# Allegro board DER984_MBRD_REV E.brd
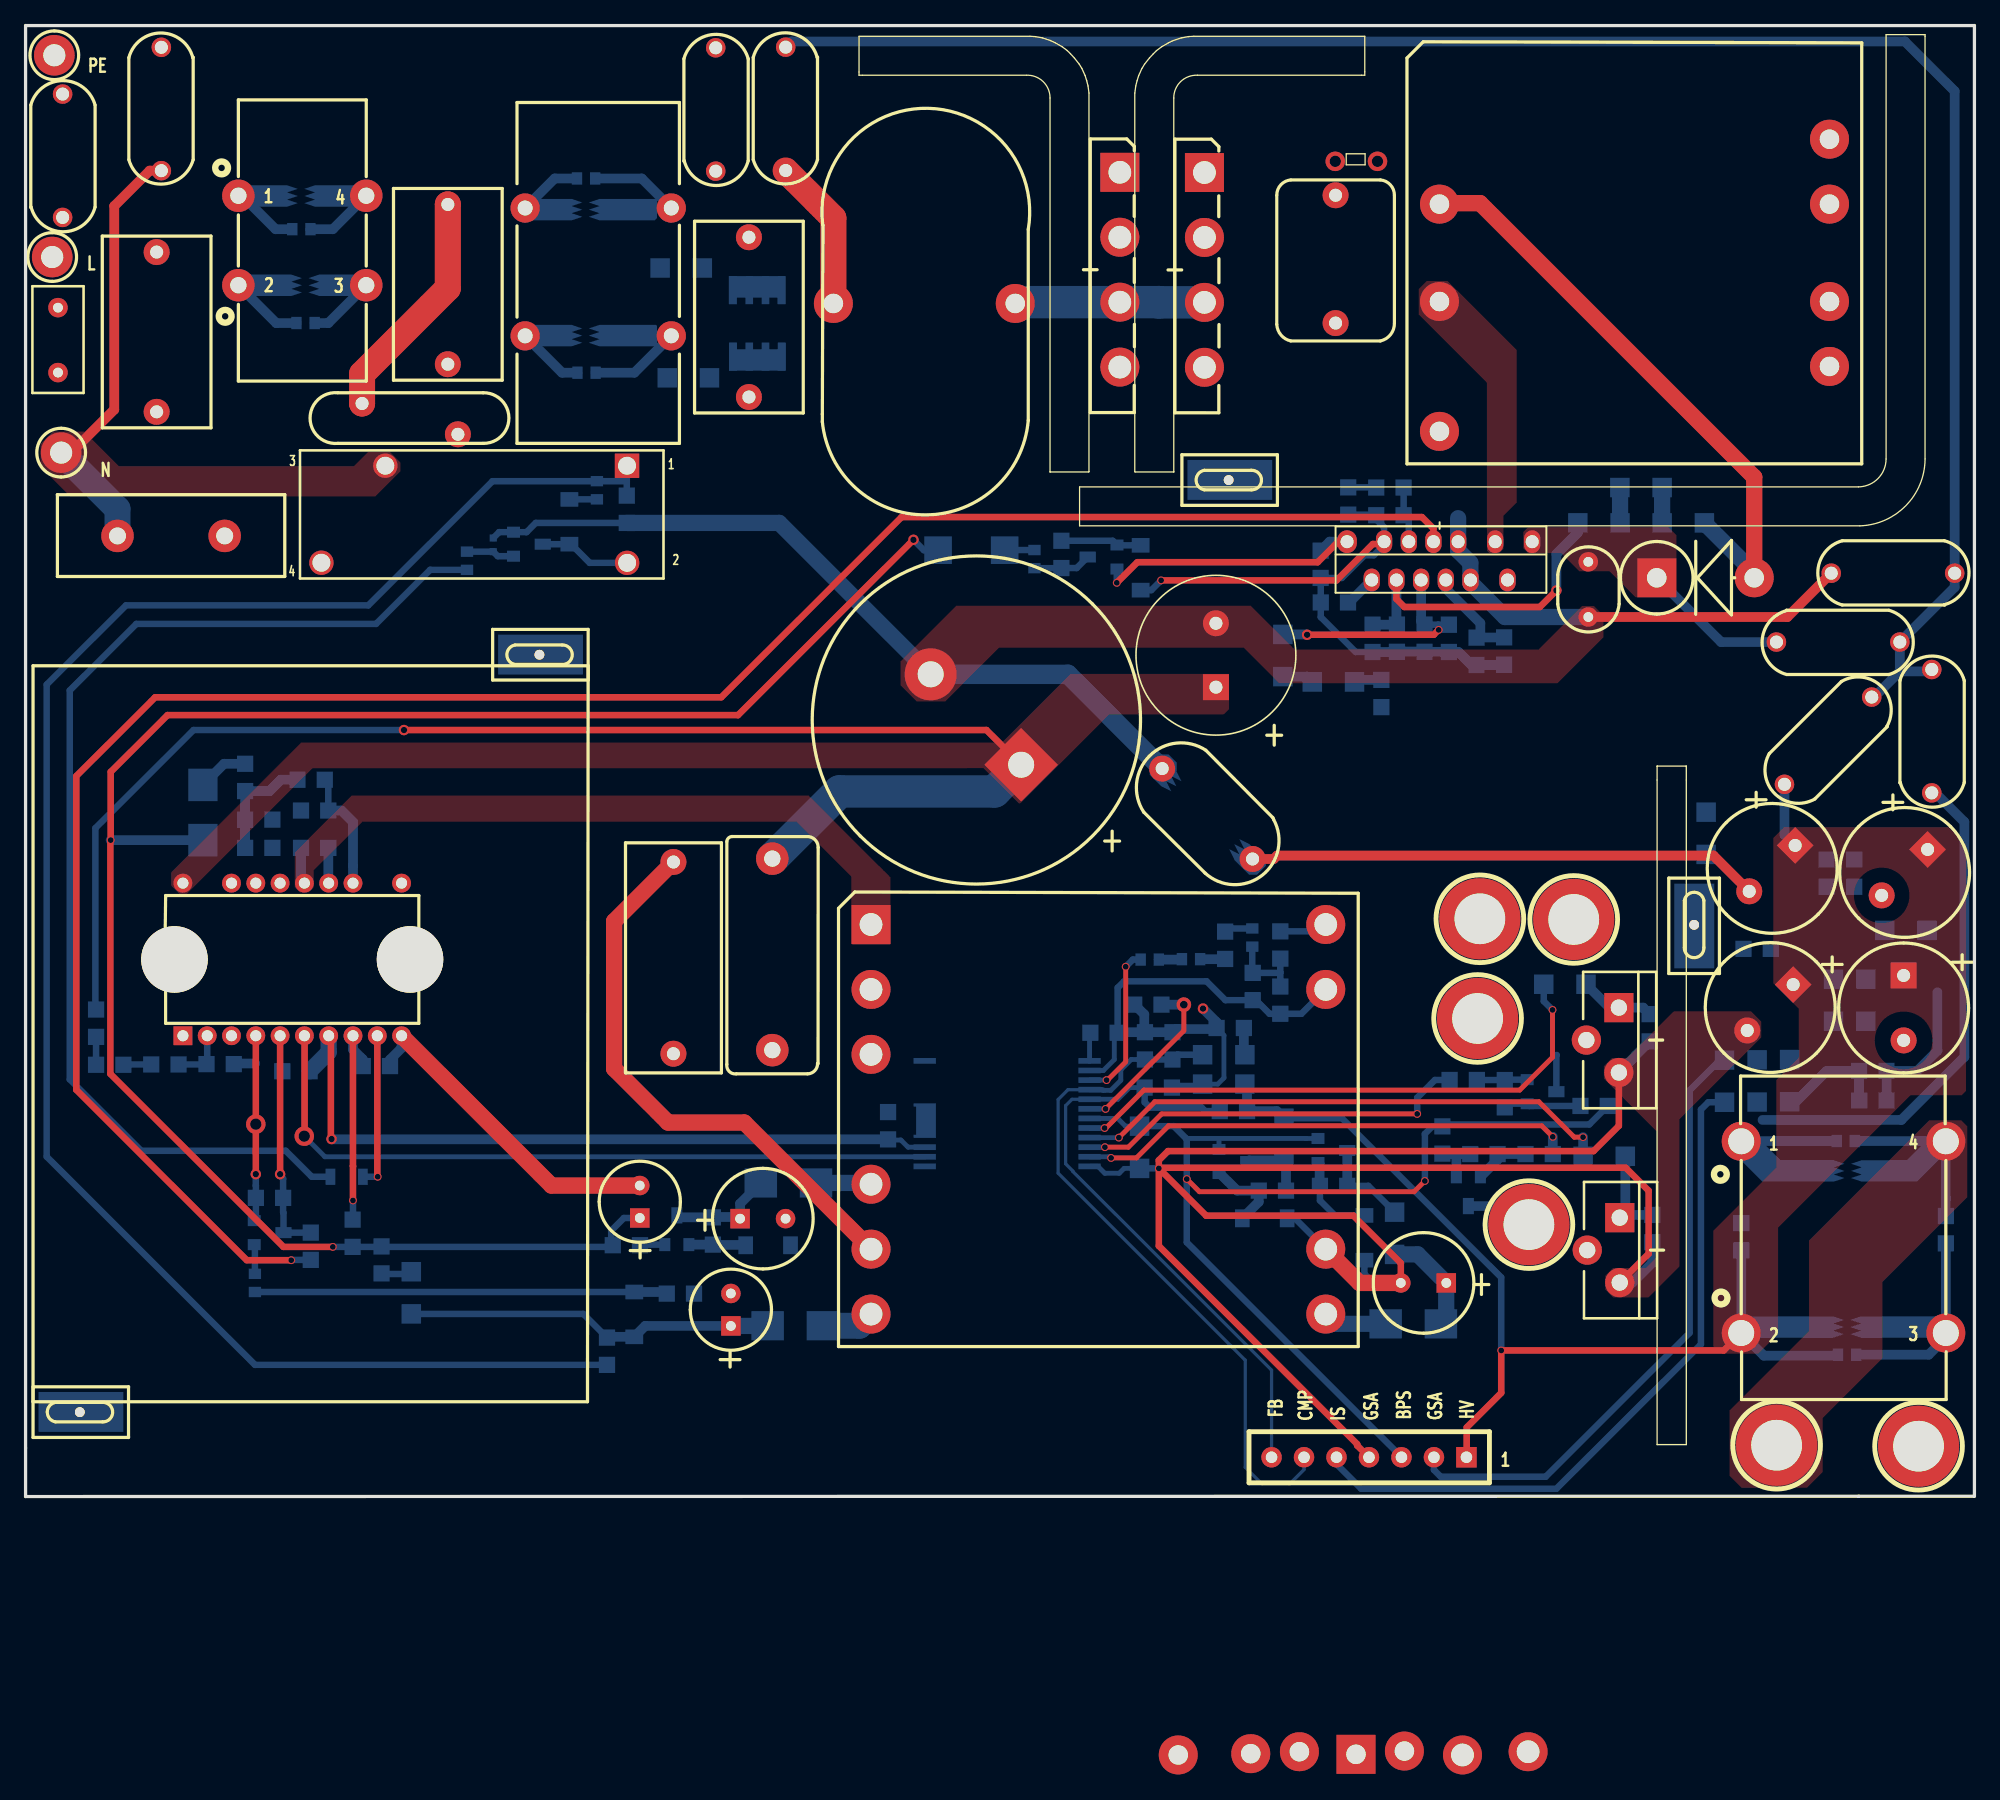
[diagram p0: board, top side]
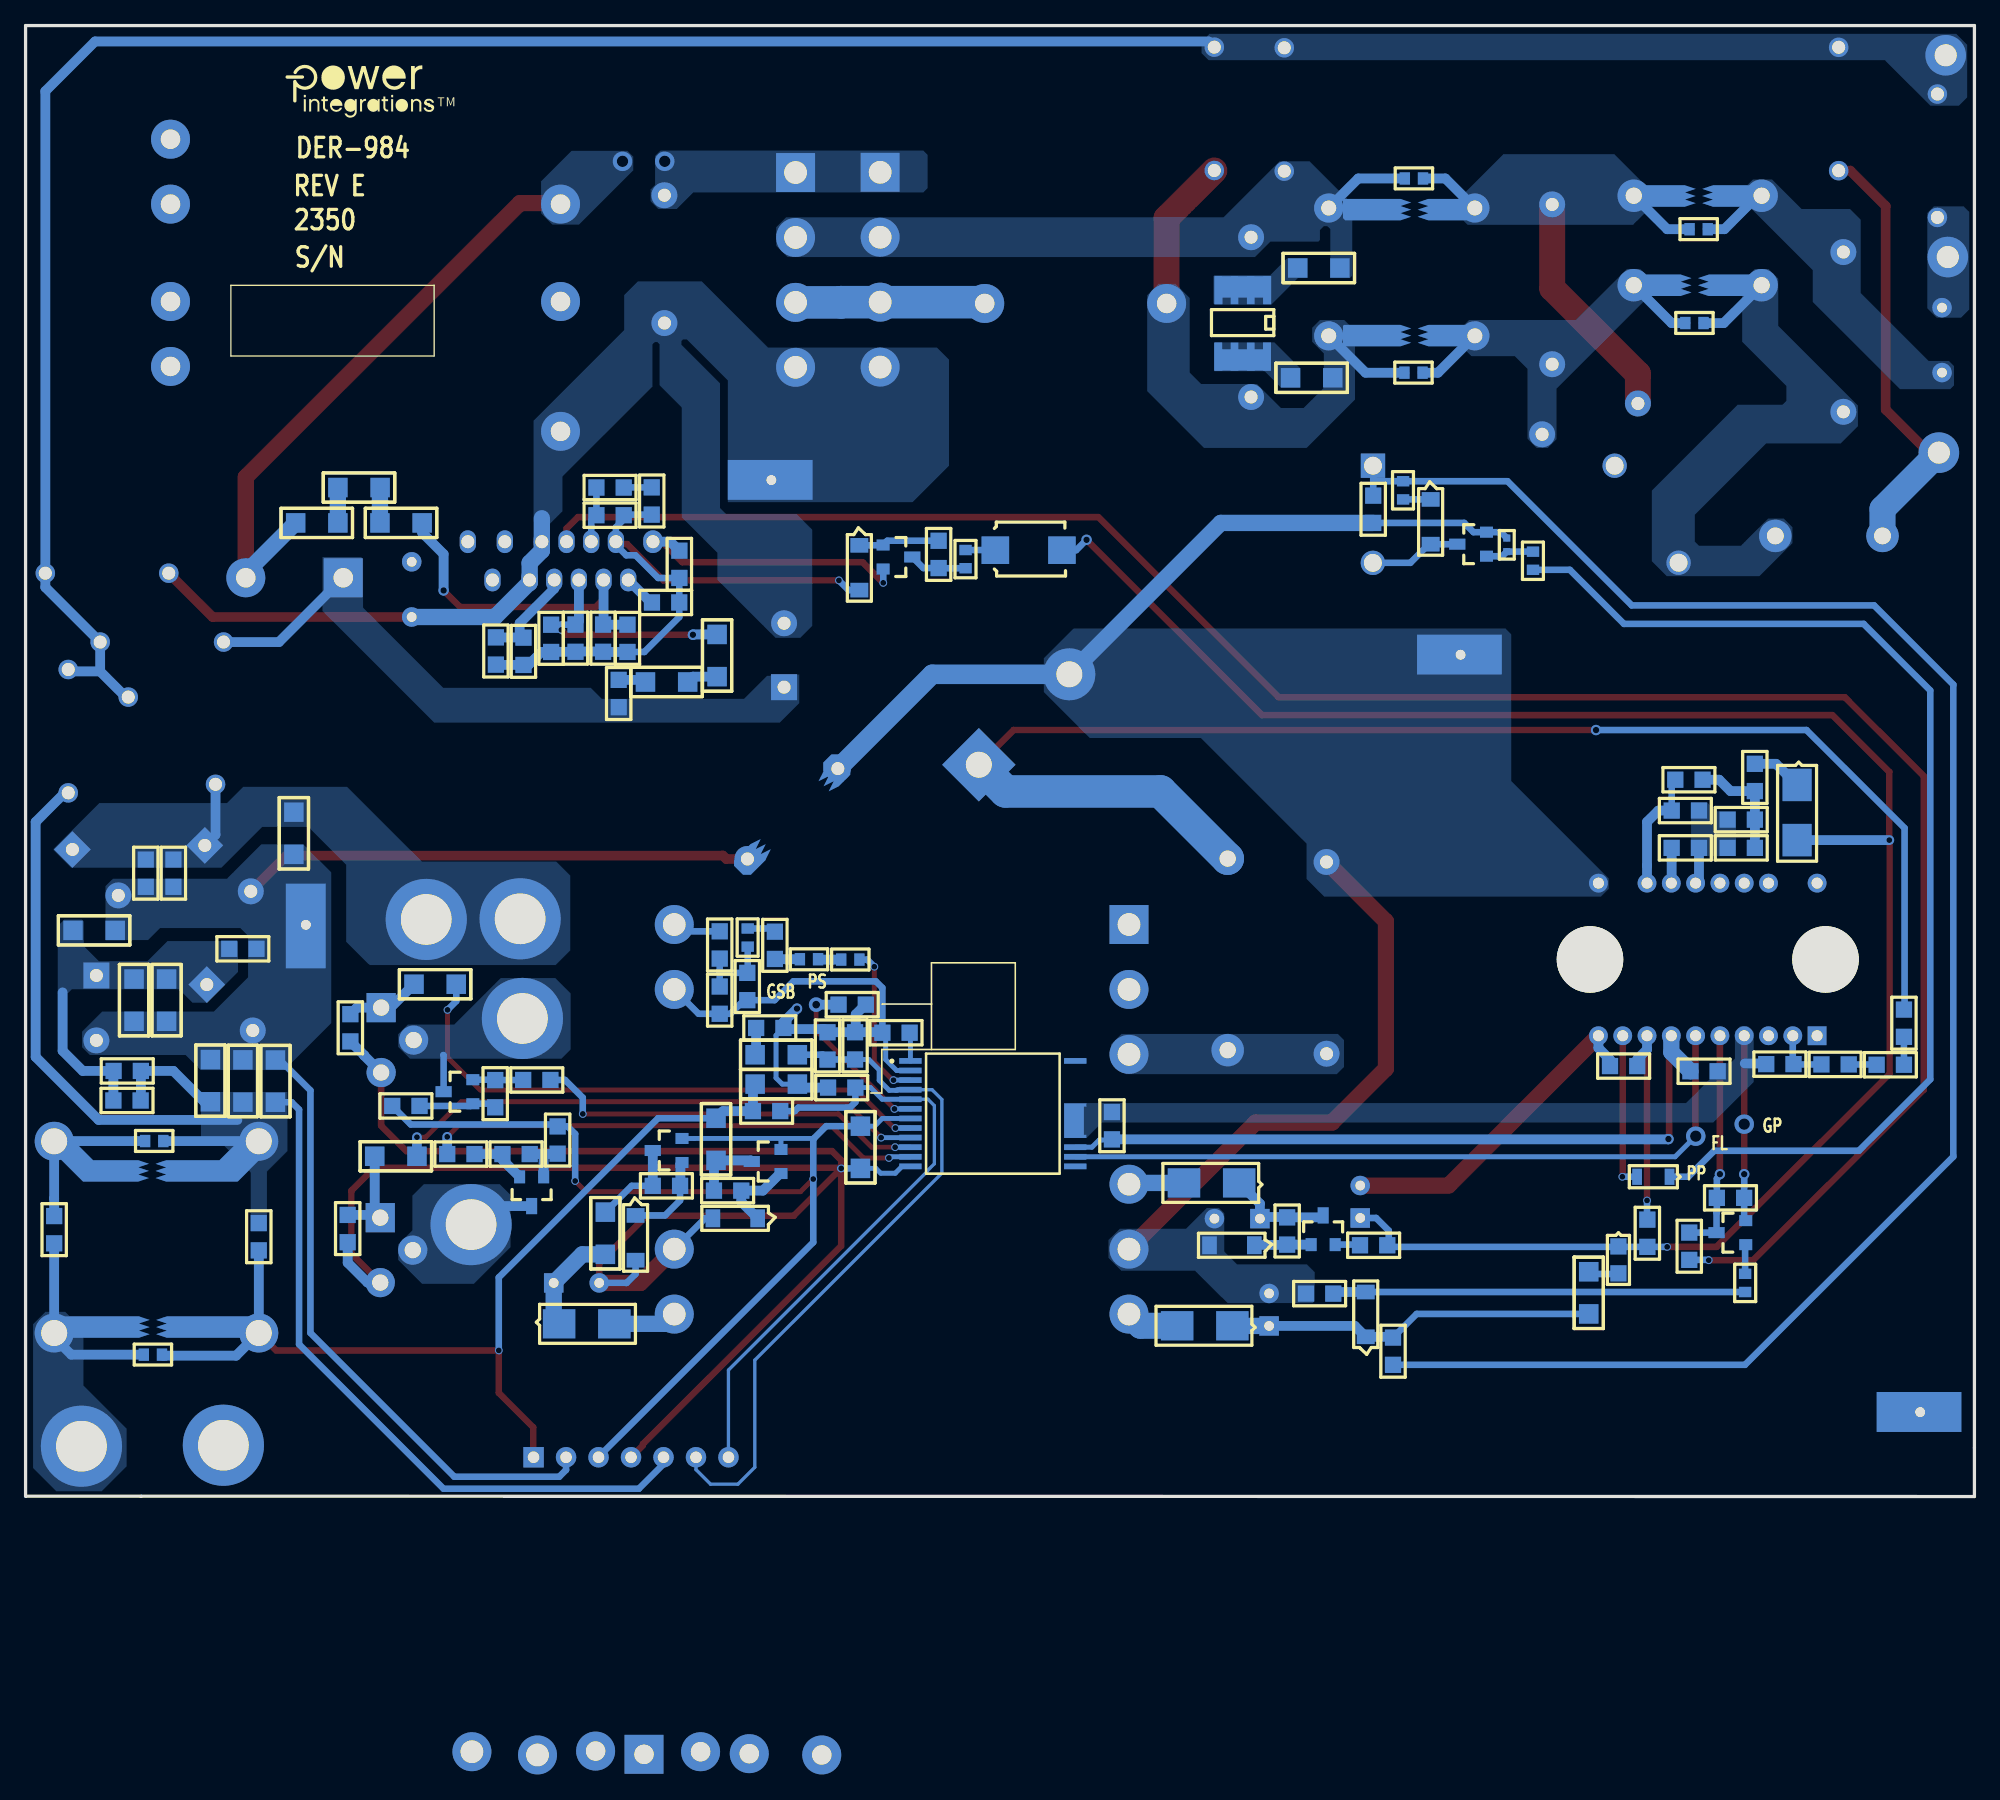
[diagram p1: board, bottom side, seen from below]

Outline 152.4 x 115.09 mm; copper layers: TOP, BOTTOM. Coordinates in mm from the lower left corner of the outline.
Outline path: 0,115.09 0,0 143.36,0.03 152.4,0.03 152.4,115.09 0,115.09

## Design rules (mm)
constraint set DEFAULT: min track width 0.254
net group 5VL: nets 5VL N12570782
net group N12371579: nets N12371579 N12371917
net group N12722777: nets N12722777 N12722869
net group 5VS: nets 5VS BOOST_OP_POS BP_RELAY CC_COMP IBSENSE N4415619 N11972126 N12371547 N12371615 N12371639 N12371737 N12371921 N12449925 N12461790 N12465647 N12472558 N12474629 OVP RTN VRECT
net group N4411203: nets N4411203

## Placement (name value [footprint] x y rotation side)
BR1  GBU8K-BP  [PIDAXBRIDGEGBU8]  92.19 103.59 270 top
BR2  GBU8K-BP  [PIDAXBRIDGEGBU8]  85.57 103.61 270 top
C1  1 uF  [PISMC0805]  21.54 53.67 0 bottom
C2  220 nF  [PISMC0805]  23.68 50.75 180 bottom
C3  100 uF  [PIPOLCAPCLYD320LS140030]  55.87 21.74 0 top
C4  10 uF  [PISMC0805]  17.17 50.75 0 bottom
C5  10 uF  [PISMC0805]  17.17 52.96 0 bottom
C7  1 uF  [PISMC0805]  26.37 33.68 0 bottom
C8  0.027 uF  [PINPXCAPRAD18X7P5MM040]  50.66 34.65 90 top
C10  150 uF  [PIPOLCAPCLYD320LS140030]  111.1 16.71 180 top
C11  220 uF  [PIPOLCAPCYLD400LS200040]  138.23 40.06 225 top
C12  100 uF  [PIPOLCAPCYLD250LS100030]  48.03 21.79 90 top
C13  100 uF  [PIPOLCAPCYLD250LS100030]  55.16 13.35 90 top
C14  1 uF  [PISMC0805]  22.21 33.27 180 bottom
C15  150 pF  [PINPCAPRAD394X275394030]  88.88 56.95 315 top
C16  1 uF  [PISMC0805]  136.48 42.85 180 bottom
C17  220 uF  [PIPOLCAPCYLD400LS200040]  138.38 50.94 225 top
C18  220 uF  [PIPOLCAPCYLD400LS200040]  148.74 50.62 225 top
C19  1 uF  [PISMC0805]  140.84 49.84 270 bottom
C20  1 uF  [PISMC0805]  143 49.84 270 bottom
C21  220 uF  [PIPOLCAPCYLD400LS200040]  146.86 40.77 270 top
C23  1.5 nF  [PISMC1206]  95.35 32.27 180 bottom
C24  10 uF  [PISMC1206]  87.11 28.98 270 bottom
C25  100 pF  [PISMC0805]  87.54 34.19 90 bottom
C26  2.2 nF  [PISMC0805]  95.27 36.66 180 bottom
C28  470 pF  [PISMC0603]  95.93 44.44 270 bottom
C30  100 nF  [PISMC0805]  67.44 27.95 90 bottom
C31  10 uF  [PISMC0805]  83.27 36.29 0 bottom
C32  680 pF  [PINPYCAPRAD470X210LS380040]  2.9 100.08 90 top
C33  680 pF  [PINPYCAPRAD470X210LS380040]  53.97 103.7 90 top
C34  1 uF  [PINPCAPRAD_12P6X9P2_LS10_D40]  102.44 101.81 270 top
C35  330 nF  [PINP_XCAPRAD15X8P5X14HD040]  33.02 101.09 270 top
C36  330 nF  [PINP_XCAPRAD15X8P5X14HD040]  56.57 98.53 270 top
C37  680 pF  [PINPYCAPRAD470X210LS380040]  59.44 113.4 270 top
C38  680 pF  [PINPYCAPRAD470X210LS380040]  10.62 113.39 270 top
C39  10 uF  [PISMC0805]  47.02 78.31 270 bottom
C40  220 uF  [PI_POLCAP_D1000LS394D080]  77.84 57.24 135 top
C41  10 nF  [PI_NP_CAP250X200LS170D030]  122.2 73.13 270 top
C42  100 nF  [PISMC0805]  107.76 76.78 180 bottom
C43  1 nF  [PISMC0805]  113.47 67.2 270 bottom
C44  1 uF  [PISMC0805]  103.42 69.95 180 bottom
C45  470 pF  [PISMC0805]  107.24 68.22 270 bottom
C46  1 uF  [PISMC0805]  103.43 78.96 270 bottom
C47  1 uF  [PISMC0805]  101.27 74 270 bottom
C48  470 pF  [PISMC0805]  109.4 68.22 270 bottom
C49  56 uF  [PIPOLCAPCLYD500LS200040]  93.09 63.32 90 top
C54  680 pf  [PISMC0805]  98.12 44.22 270 bottom
C58  6.8 nF  [PI_NP_CAPRAD709X276LS590D050]  58.39 49.91 270 top
C60  330 nF  [PINP_XCAPRAD15X8P5X14HD040]  10.25 97.37 270 top
C61  680 pF  [PINPYCAPRAD470X210LS380040]  136.92 66.85 0 top
C62  680 pF  [PINPYCAPRAD470X210LS380040]  150.86 72.24 180 top
C63  1 uF  [PISMC0805]  143.38 33.3 0 bottom
C64  680 pF  [PINPYCAPRAD470X210LS380040]  149.06 55.05 90 top
C65  680 pF  [PINPYCAPRAD470X210LS380040]  144.37 62.55 225 top
C68  100 nF  [PISMC0805]  143.4 30.99 0 bottom
C69  100 nF  [PISMC0805]  134.16 21.4 270 bottom
C70  100 nF  [PISMC0805]  150.16 21.95 270 bottom
C71  100 pF  [PISMC0805]  95.96 40.97 270 bottom
D1  ES1A-13-F  [PISMDO214AC12]  57.5 24.54 0 bottom
D2  BAV16WS-7-F  [PISMSOD323]  23.84 25.02 0 bottom
D3  ES1J-LTP  [PISMDO214AC12]  13.87 55.68 270 bottom
D4  BAS16HT1G  [PISMDSOD323]  27.84 19.57 270 bottom
D5  ES1A-13-F  [PISMDO214AC12]  58.03 13.36 0 bottom
D6  ES1A-13-F  [PISMDO214AC12]  110.68 13.51 180 bottom
D7  1N4148W RHG  [PI_SM_SOD-123_12]  42.52 78.02 270 bottom
D8  1N5408G  [PIDV300X200X060DO15D0201AD]  127.56 71.88 0 top
D11  S1AB-13-F  [PISMSMB]  76.56 74.04 180 bottom
F1  6.3 A  [PI_V_AX_BEL_0697H]  2.53 93.02 270 top
FL2  Hole_156mils  [PI_HOLE_156MIL]  113.73 45.2 0 top
FL3  Hole_156mils  [PI_HOLE_156MIL]  121.07 45.15 0 top
FL4  Hole_156mils  [PI_HOLE_156MIL]  117.56 21.28 0 top
FL5  Hole_156mils  [PI_HOLE_156MIL]  113.55 37.4 0 top
GND1  Hole_156mils  [PI_HOLE_156MIL]  136.93 4.01 0 top
HS3  Terminal, Eyelet, Zierick 190  [PI_ZIERICK190_EYELET]  94.08 79.53 180 top
HS4  Terminal, Eyelet, Zierick 190  [PI_ZIERICK190_EYELET]  40.18 65.86 180 top
HS5  Terminal, Eyelet, Zierick 190  [PI_ZIERICK190_EYELET]  130.48 44.73 90 top
HS40  Terminal, Eyelet, Zierick 190  [PI_ZIERICK190_EYELET]  4.24 6.6 180 top
J1  PCB Terminal 18 AWG  [PI_HOLE_18AWG]  2.08 97 180 top
J2  PCB Terminal 18 AWG  [PI_HOLE_18AWG]  2.25 112.74 0 top
J3  PCB Terminal 18 AWG  [PI_HOLE_18AWG]  2.78 81.65 0 top
J8  CON7  [PI_HDRF_1X7_HIROSE]  112.67 3.07 180 top
L1  9 mH  [PI_IND_4P_500X1050LS450D46]  39.07 100.81 0 top
L2  390 uH  [PITOROID2P650X1170LS560060]  63.17 93.34 0 top
L4  1 mH  [PI_CMC_1MH]  21.64 98.27 270 top
L5  500 uH  [PI_CMC_500UH]  142.16 20.29 270 top
NOREF  -  []  0 0.03 0 top
NOREF#2  -  []  152.4 0.03 90 top
NOREF#3  -  []  -124.37 52.43 0 top
NOREF#4  -  []  -212.01 -91.44 0 top
NOREF#5  -  []  132.05 112.45 180 bottom
Q1  MMBTA06LT1  [PISMSOT23123_1]  49.99 19.71 180 bottom
Q2  MMBT4401LT1G  [PISMSOT23123_1]  85.34 72.57 270 bottom
Q3  MMBTA06LT1  [PISMSOT23123_1]  17.88 21.59 90 bottom
Q4  PMBTA06,215  [PISMSOT23123_1]  101.07 28.01 90 bottom
Q5  IPP111N15N3 G  [PITO220ABVF1]  124.59 38.25 270 top
Q6  TN2130K1-G  [PISMSOT23123_1]  117.42 32.61 90 bottom
Q7  FMMT493TA  [PISMSOT23123_1]  93.33 27.15 90 bottom
Q9  TN2130K1-G  [PISMSOT23123_1]  113.77 25.01 0 bottom
Q10  BSS169H6327XTSA1  [PISMSOT23123_1]  38.16 75.45 90 bottom
Q11  IPP111N15N3 G  [PITO220ABVF1]  124.66 21.82 270 top
R1  11.0  [PISMR0805]  23.39 56.08 180 bottom
R2  10 k  [PISMR0805]  53.75 21.84 270 bottom
R3  2.2  [PISMR0805]  17.17 55.19 90 bottom
R6  11  [PISMR0805]  25.58 21.67 270 bottom
R7  47 k  [PISMR0603]  17.93 16 90 bottom
R9  316 k  [PISMR0805]  20.14 23.37 180 bottom
R10  10  [PISMR1206]  107.06 18.95 90 bottom
R11  100  [PISMR0805]  50.14 15.88 0 bottom
R12  10 k  [PISMR0805]  103.35 24.31 180 bottom
R13  340 k  [PISMR0805]  95.52 30.16 180 bottom
R16  22.1 k  [PISMR0805]  87.51 32 0 bottom
R18  0.015  [PISMR1206]  132.86 34.15 270 bottom
R19  10 k  [PISMR0805]  127 35.61 90 bottom
R20  200  [PISMR0805]  123.73 30.56 180 bottom
R21  2.2  [PISMR1206]  122.02 40.08 180 bottom
R22  20  [PISMR1206]  98.41 26.3 90 bottom
R23  511 k  [PISMR0805]  115.67 30.45 90 bottom
R24  10 k  [PISMR0805]  98.57 23.93 180 bottom
R25  1 k  [PISMR0805]  113.49 32.59 180 bottom
R26  0.015  [PISMR1206]  135.4 34.17 270 bottom
R27  200  [PISMR0805]  110.79 28.96 270 bottom
R28  10 k  [PISMR0805]  127.21 19.9 90 bottom
R29  2.2  [PISMR1206]  125.1 26.62 180 bottom
R31  511 k  [PISMR0805]  112.98 26.79 0 bottom
R32  1 k  [PISMR0805]  117.29 26.79 0 bottom
R34  150 k  [PISMR1206]  92.05 34.57 0 bottom
R36  750 k  [PISMR0603]  87.2 42.01 0 bottom
R37  750 k  [PISMR0603]  91.85 42.04 180 bottom
R38  162 k  [PISMR0805]  93.8 42.06 90 bottom
R40  499 k  [PISMR0805]  88.83 38.48 180 bottom
R42  510 k  [PISMR1206]  49.62 96.12 0 bottom
R43  510 k  [PISMR1206]  53.48 87.53 180 bottom
R44  10  [PISMR0603]  44.68 79.44 270 bottom
R45  4.7 k  [PISMR0603]  34.52 73.93 270 bottom
R46  10 k  [PISMR0402]  36.57 73.93 90 bottom
R47  3.6 M  [PISMR0805]  106.02 61.76 90 bottom
R48  6.2 M  [PISMR1206]  131.28 76.17 180 bottom
R49  6.2 M  [PISMR1206]  103.92 63.73 180 bottom
R50  6.2 M  [PISMR1206]  127.98 78.94 180 bottom
R51  3.74 M  [PISMR1206]  124.69 76.17 180 bottom
R52  2.2  [PISMR0603]  78.89 74.05 270 bottom
R53  332 k  [PISMR0805]  115.62 67.22 270 bottom
R54  13.0 k  [PISMR0805]  107.76 78.94 180 bottom
R55  6.2 M  [PISMR1206]  98.32 64.15 90 bottom
R56  158 k  [PISMR0805]  105.33 68.21 270 bottom
R57  162 k  [PISMR0805]  111.3 68.21 270 bottom
R58  120  [PISMR1206]  30.16 17.59 270 bottom
R60  0.015  [PISMR1206]  137.95 34.19 270 bottom
R63  1.5 M  [PISMR0805]  5.51 33.78 0 bottom
R64  1 M  [PISMR0805]  9.83 33.81 0 bottom
R65  1.5 M  [PISMR0805]  5.51 38.1 270 bottom
R71  10 k  [PISMR0805]  81 72.64 90 bottom
R72  18.2 k  [PISMR0805]  22.3 18.52 90 bottom
R73  0.0  [PISMR0805]  14.15 33.83 0 bottom
R74  10 M  [PISMR0805]  89.69 34.19 90 bottom
R75  11.8 k  [PISMR0805]  98.12 39.9 270 bottom
R77  24.9 k  [PISMR1206]  143.92 40.49 270 bottom
R78  24.9 k  [PISMR1206]  148.69 44.3 180 bottom
R79  24.9 k  [PISMR1206]  131.42 53.54 270 bottom
R80  24.9 k  [PISMR1206]  141.38 40.49 270 bottom
R81  1.1  [PISMR0805]  45.91 19.66 0 bottom
R82  120  [PISMR0805]  45.47 10.3 90 bottom
R83  100 K  [PISMR0603]  43.12 103.12 0 bottom
R84  100 K  [PISMR0603]  43.15 87.93 0 bottom
R85  100 K  [PISMR0603]  20.85 99.15 0 bottom
R86  100 K  [PISMR0603]  21.18 91.81 0 bottom
R87  100 K  [PISMR0603]  141.63 27.81 0 bottom
R88  100 K  [PISMR0603]  141.73 11.1 0 bottom
RL1  SPST NO  [PI_RLY-OMRON-G6RL-1A]  47.01 80.66 180 top
RT1  16  [PIRAD800X250LS330052]  7.19 75.16 0 top
RV1  320 Vac  [PIDISC610X212LS295X95040]  26.31 85.52 0 top
T1  PQ35/35  [PI_BOBBIN_BPQ35_35_12P]  66.11 44.75 0 top
T2  PQ32/20  [PI_BOBBIN_BPQ32_20_12P]  110.57 111.28 0 top
U1  LCS7268Z  [PI_POWEDIP_B18PA]  20.85 42.02 0 top
U4  LSR2000C-H010  [PI_IC_INSOP_24D]  83.21 34.08 180 bottom
U5  CAP003DG  [PI_IC_SMD_SO8_CAPZERO]  55.32 94.39 0 bottom
U6  PFS7539H  [PI_IC_EESIP_SOCKET]  103.34 74.71 0 top
UNK+60V1  Hole_156mils  [PI_HOLE_156MIL]  148.03 3.94 0 top
VR1  MMSZ5250B-7-F  [PI_SM_SOD-123_12]  56.31 19.66 0 bottom
VR2  MMSZ5259BT1G  [PI_SM_SOD-123_12]  47.6 12.5 90 bottom
VR3  MMSZ5242C-E3-08  [PI_SM_SOD-123_12]  87.2 74.42 270 bottom
VR4  MMSZ5243BT1G  [PI_SM_SOD-123_12]  104.7 22 270 bottom
VR6  MMSZ5242B-7-F  [PI_SM_SOD-123_12]  95.15 21.77 0 bottom

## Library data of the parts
BR1 BR2 = DISCRETE BRIDGE_+~~-
C1 C2 C7 C14 = CAP NP: room: 1
C3 = CAP POL: room: 1
C4 C5 = CAP NP: alternate symbols: (pismc0805_1); room: 1
C8 = CAP NP: alternate symbols: (pinpxcaprad18x7p5x13p6mm040H); room: 1
C10 C13 C40 = CAP POL
C11 C17 C18 C21 = CAP POL: alternate symbols: (pipolcapcyld400ls200040800h)
C12 = CAP POL: alternate symbols: (pipolcapcyld250ls100030h)
C15 = CAP NP: tolerance: 20; room: 1
C16 C19 C20 C23 C25 C26 C28 C30 C31 C63 C68-C70 = CAP NP: room: 2
C24 = CAP NP: alternate symbols: (CC1206); room: 2
C32 C33 C37 C38 C61 C62 C64 C65 = CAP NP: tolerance: 20
C34 = CAP NP: alternate symbols: (pinpcaprad_12p6x9p2_ls10_d400H)
C35 C36 C60 = CAP NP: alternate symbols: (pinp_xcaprad15x8p5x14Hd040H)
C39 = CAP NP: alternate symbols: (pismc0805_1)
C41-C48 = CAP NP
C49 = CAP POL: alternate symbols: (pipolcapclyd500ls2000401200lh)
C54 C71 = CAP NP: alternate symbols: (Unisem_RMCF0805UL)
C58 = CAP NP: alternate symbols: (pi_np_caprad709x276ls590d050_h); room: 1
D1-D6 = DIODE: room: 1
D7 = DIODE: alternate symbols: (pi_sm_sod-123_12_1)
D8 = DIODE: alternate symbols: (pidv300x472x060do14wbead,pidax800x225060do15do201ad,pidv300x200x060do14wbead)
D11 = DIODE
F1 = FUSE: alternate symbols: (PI_V_AX_BEL_0697H_H)
FL2-FL5 GND1 UNK+60V1 = FlyingLead: room: 2
HS3-HS5 HS40 = TERM EYLT
J1-J3 = TERM_1Pin
J8 = HEADER 7
L1 = INDUCTOR_4P_revB
L2 = INDUCTOR
L4 L5 = TORRID 4P_14_23
Q1 Q3 Q4 = NPN_BEC: room: 1
Q2 = NPN_BEC
Q5 Q11 = FET_N_GDS: alternate symbols: (PI_TO220AB,PITO220ABVF1R,pidvto2203vf1h); room: 2
Q6 Q9 Q10 = FET_N_GSD
Q7 = NPN_BEC: room: 2
R1-R3 R6 R7 R9-R12 R81 = R: room: 1
R13 R16 R19-R21 R23 R24 R27-R29 R31 R34 R36 R37 R40 R74 = R: room: 2
R18 R22 R25 R26 R32 R42-R56 R58 R60 R63-R65 R71 R72 R77-R80 R82-R88 = R
R38 = R: alternate symbols: (Unisem_RMCF0805UL); room: 2
R57 = R: alternate symbols: (Unisem_RMCF0805UL)
R73 = R: alternate symbols: (pismr0805_1)
R75 = R: alternate symbols: (Unisem_RMCF0805UL); room: 1
RL1 = RELAY SPST_NO_OMRON-G6RL
RT1 = THERMISTOR
RV1 = VARISTOR
T1 = BPQ35/35_12P/GENERIC
T2 = BPQ32/20_12P/GENERIC
U1 = HiperLCS2-HB: alternate symbols: (pi_PoweDIP_B18pNH)
U4 = HiperLCS2-SR
U5 = CAPZero
U6 = DEV_HIPERPFS-3-eSIP-16C: alternate symbols: (pi_ic_esip16-13_socket_hpii ,pi_ic_esip16-13_oval_hpii,pi_ic_eesip_socket)
VR1 VR2 VR4 = DIODE_ZENER: room: 1
VR3 = DIODE_ZENER
VR6 = DIODE_ZENER: room: 2

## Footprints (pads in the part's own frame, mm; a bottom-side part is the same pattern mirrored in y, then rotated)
PI_BOBBIN_BPQ32_20_12P
  rect 3.048x3.048 hole 1.524: 1(-6.528,-131.445)
  round 3.048 hole 1.524: 2(-14.757,-131.394) 3(0,-10.16) 4(0,-17.78) 5(-2.743,-131.191) 6(0,-27.94) 7(-20.427,-131.496) 8(30.5,-22.86) 9(30.5,-17.78) 10(30.5,-10.16) 11(30.5,-5.08) 12(-10.952,-131.242)
PI_BOBBIN_BPQ35_35_12P
  rect 3.048x3.048 hole 1.778: 1(0,0)
  round 3.048 hole 1.778: 2(0,-5.08) 3(0,-10.16) 4(0,-20.32) 5(0,-25.4) 6(0,-30.48) 7(35.56,-30.48) 8(35.56,-25.4) 9(46.253,-64.973) 10(51.384,-64.719) 11(35.56,-5.08) 12(35.56,0)
PI_CMC_1MH
  round 2.54 hole 1.27: 1(-3.5,-5) 2(3.5,-5) 3(3.5,5) 4(-3.5,5)
PI_CMC_500UH
  round 3.048 hole 2.032: 1(-7.5,-8) 2(7.5,-8) 3(7.5,8) 4(-7.5,8)
PI_HDRF_1X7_HIROSE
  rect 1.6x1.6 hole 0.9: 1(0,0)
  round 1.6 hole 0.9: 2(2.54,0) 3(5.08,0) 4(7.62,0) 5(10.16,0) 6(12.7,0) 7(15.24,0)
PI_HOLE_18AWG
  round 3.175 hole 1.727: 1(0,0.025)
PI_HOLE_156MIL
  round 6.35 hole 3.962: 1(0,0)
PI_IC_EESIP_SOCKET
  oval 1.524x1.778 hole 1.016: 1(0,0)
  oval 1.27x1.778 hole 1.016: 3(1.93,-2.997) 4(2.896,0) 5(3.861,-2.997) 6(4.826,0) 7(5.791,-2.997) 8(6.756,0) 9(7.722,-2.997) 10(8.687,0) 11(9.652,-2.997) 13(11.582,0) 14(12.548,-2.997) 16(14.478,0)
PI_IC_INSOP_24D
  rect 1.75x0.45 smd: 1(0,0) 2(0,-0.749) 3(0,-1.501) 4(0,-2.25) 5(0,-3) 6(0,-3.749) 7(0,-4.501) 8(0,-5.25) 9(0,-5.999) 10(0,-6.749) 11(0,-7.501) 12(0,-8.25) 13(12.89,-8.25) 14(12.89,-7.501) 15(12.89,-6.749) 24(12.89,0)
  custom 0.437x0.437 smd: 16(12.89,-4.671)
PI_IC_SMD_SO8_CAPZERO
  rect 0.599x2.2 smd: 1(0,0) 2(1.27,0) 3(2.54,0) 4(3.81,0) 5(3.81,5.199) 6(2.54,5.199) 7(1.27,5.199) 8(0,5.199)
PI_IND_4P_500X1050LS450D46
  round 2.286 hole 1.168: 1(0,0) 2(11.43,0) 3(0,-10) 4(11.43,-10)
PI_NP_CAP250X200LS170D030
  round 1.524 hole 0.762: 1(0,0) 2(4.318,0)
PI_NP_CAPRAD709X276LS590D050
  round 2.54 hole 1.27: 1(0,0) 2(14.986,0)
PI_POLCAP_D1000LS394D080
  rect 4.064x4.064 hole 2.032: 1(0,-0.025)
  round 4.064 hole 2.032: 2(10.008,-0.025)
PI_POWEDIP_B18PA
  round 5.199 hole 5.199 unplated: (-9.21,0) (9.21,0)
  rect 1.473x1.473 hole 0.864: 1(-8.55,-5.97)
  round 1.473 hole 0.864: 2(-6.65,-5.97) 3(-4.75,-5.97) 4(-2.85,-5.97) 5(-0.95,-5.97) 6(0.95,-5.97) 7(2.85,-5.97) 8(4.75,-5.97) 9(6.65,-5.97) 10(8.55,-5.97) 11(8.55,5.97) 13(4.75,5.97) 14(2.85,5.97) 15(0.95,5.97) 16(-0.95,5.97) 17(-2.85,5.97) 18(-4.75,5.97) 20(-8.55,5.97)
PI_RLY-OMRON-G6RL-1A
  rect 1.905x1.905 hole 1.397: 1(-0.02,0.008)
  round 1.905 hole 1.397: 2(-0.03,7.607) 3(18.88,0.008) 4(23.879,7.597)
PI_SM_SOD-123_12
  rect 1.143x1.397 smd: 1(0,0) 2(3.505,0)
PI_V_AX_BEL_0697H
  round 1.524 hole 0.762: 1(0,0) 2(5.08,0)
PI_ZIERICK190_EYELET
  round 0.762 hole 0.762: 1(0,0)
PIDAXBRIDGEGBU8
  rect 3.048x3.048 hole 1.778: 1(0,0)
  round 3.048 hole 1.778: 2(5.08,0) 3(10.16,0) 4(15.24,0)
PIDISC610X212LS295X95040
  round 2.032 hole 1.016: 1(0,0) 2(7.493,-2.413)
PIDV300X200X060DO15D0201AD
  rect 3.048x3.048 hole 1.524: 1(0,0)
  round 3.048 hole 1.524: 2(7.62,0)
PINP_XCAPRAD15X8P5X14HD040
  round 2.032 hole 1.016: 1(0,0) 2(12.5,0)
PINPCAPRAD394X275394030
  round 2.032 hole 1.016: 1(0,0) 2(10,0)
PINPCAPRAD_12P6X9P2_LS10_D40
  round 2.032 hole 1.016: 1(0,0) 2(10,0)
PINPXCAPRAD18X7P5MM040
  round 2.032 hole 1.016: 1(0,0) 2(15,0)
PINPYCAPRAD470X210LS380040
  round 1.524 hole 1.016: 1(0,0) 2(9.652,0)
PIPOLCAPCLYD320LS140030
  rect 1.524x1.524 hole 0.762: 1(0,0)
  round 1.524 hole 0.762: 2(3.556,0)
PIPOLCAPCLYD500LS200040
  rect 2.032x2.032 hole 1.016: 1(0,0)
  round 2.032 hole 1.016: 2(5.001,0)
PIPOLCAPCYLD250LS100030
  rect 1.524x1.524 hole 0.762: 1(0,0)
  round 1.524 hole 0.762: 2(2.54,0)
PIPOLCAPCYLD400LS200040
  rect 2.032x2.032 hole 1.016: 1(0,0)
  round 2.032 hole 1.016: 2(5.08,0)
PIRAD800X250LS330052
  round 2.54 hole 1.321: 1(0,0) 2(8.382,0)
PISMC0603
  rect 0.813x0.965 smd: 1(0,0) 2(1.422,0)
PISMC0805
  rect 1.27x1.27 smd: 1(0,0) 2(2.134,0)
PISMC1206
  rect 1.524x1.524 smd: 1(0,0) 2(3.302,0)
PISMDO214AC12
  rect 2.54x2.286 smd: 1(0,0) 2(4.318,0)
PISMDSOD323
  rect 1.27x1.27 smd: 1(0,0) 2(2.108,0)
PISMR0402
  rect 0.559x0.559 smd: 1(0,0) 2(1.067,0)
PISMR0603
  rect 0.813x0.965 smd: 1(0,0) 2(1.422,0)
PISMR0805
  rect 1.27x1.27 smd: 1(0,0) 2(2.134,0)
PISMR1206
  rect 1.524x1.524 smd: 1(0,0) 2(3.302,0)
PISMSMB
  rect 2.159x2.159 smd: 1(0,0) 2(5.207,0)
PISMSOD323
  rect 0.762x1.27 smd: 1(0,0) 2(2.54,0)
PISMSOT23123_1
  rect 0.864x1.016 smd: 1(-1.88,0) 2(0,0)
  rect 0.864x1.27 smd: 3(-0.94,2.286)
PITO220ABVF1
  rect 2.286x2.286 hole 1.27: 1(0,0)
  round 2.286 hole 1.27: 2(2.54,-2.54) 3(5.08,0)
PITOROID2P650X1170LS560060
  round 3.048 hole 1.524: 1(0,0) 2(14.224,0)

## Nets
5VL: C14.1 C30.1 U1.7 U4.15
5VS: C31.1 U4.1
BM: D2.1 R45.2
BOOST_OP_POS: C40.1 C41.1 C49.1 C58.1 C61.1 D8.1 R47.1 R65.1 U1.20 U6.16
BP_RELAY: C39.1 R44.1 R82.1 RL1.1
BPP: C12.1 D3.2 D4.1 D11.2 R6.2 R81.1
BPS: C24.1 J8.3 Q4.2(\EMITTER\) Q7.2(\EMITTER\) R20.1 R27.1 U4.7
CC_COMP: C25.1 J8.6 R34.1 R74.1 U4.4
CC_FB: J8.7 R13.2 R16.1 U4.5
FL: U1.6 U4.14
GD: C7.2 C12.2 U1.10
GP: C14.2 C30.2 Q3.2(\EMITTER\) R9.2 R73.2 U1.4 U4.16
GS: HS40.1
GSA: C10.2 C11.2 C15.2 C16.2 C17.2 C18.2 C19.2 C20.2 C21.2 C24.2 HS5.1 J8.2 J8.4 Q5.3(\S\) Q11.3(\S\) R18.1 R19.1 R26.1 R28.1 R60.1 R77.2 R78.2 R79.2 R80.2 T1.8 U4.12 VR4.2 VR6.2
GSB: C23.2 C25.2 C26.2 C31.2 C71.2 R16.2 R40.2 R74.2 R75.2 T1.11 U4.2
HVOUTP: C11.1 C16.1 C17.1 C18.1 C19.1 C20.1 C21.1 C23.1 C63.2 C65.2 C68.2 C69.2 FL2.1 FL3.1 J8.1 L5.2 R13.1 R22.2 R77.1 R78.1 R79.1 R80.1 R88.1
IBSENSE: C63.1 C64.1 C68.1 C69.1 J8.5 L5.1 R18.2 R26.2 R60.2 R87.1
IS: C28.2 C54.2 C71.1 R75.1
OVP: R7.1 R11.1 VR2.2
PE_GND: C32.2 C33.2 C37.1 C38.1 C61.2 C62.1 C64.2 C65.1 J2.1
PG_PFS: R72.1 U6.8
RTN: BR1.4 BR2.4 C3.2 C8.2 C13.2 C15.1 C34.2 C39.2 C40.2 C41.2 C49.2 C62.2 HS3.1 HS4.1 Q10.2(\S\) R11.2 R46.2 T1.5 T2.6 U1.11(\S\) U6.10 VR1.2
SOURCE: U6.11
VRECT: BR1.1 BR2.1 C34.1 D8.2 R48.1 T2.3
N4285024: C1.2 R1.1 U1.13
N4285032: C4.1 C5.1 R1.2 R3.1
N4285050: C1.1 C2.2 C4.2 C5.2 T1.1 U1.15
N4286456: C2.1 U1.14
N4298336: D5.2 T1.6
N4344251: Q3.3 R9.1 R72.2 U1.5
N4347891: C7.1 R6.1 U1.8
N4369660: R36.1 U4.3
N4383576: R29.2 U4.9
N4398139: FL5.1 Q5.2 Q6.3
N4403571: R21.2 U4.8
N4411199: R37.1 R38.1
N4411203: C28.1 R38.2
N4415619: C26.1 R34.2
N4433947: Q11.1 R28.2 R29.1
N4539125: Q5.1 R19.2 R21.1
N4545785: D3.1 R3.2
N11972126: C13.1 D5.1 R58.2 R82.2 VR2.1
N12003586: Q3.1 R7.2
N12025663: R25.2 U4.10
N12156031: D6.2 T1.7
N12157735: Q9.2(\S\) R31.2 R32.1
N12157737: R32.2 U4.11
N12157825: Q6.2(\S\) R23.2 R25.1
N12357991: R36.2 R37.2
N12371547: C32.1 F1.1 J1.1
N12371579: C35.1 L1.1 L4.4 R83.1 R85.2 RV1.1
N12371615: BR1.2 BR2.2 C33.1 C36.1 L1.2 R42.1 R83.2
N12371639: BR1.3(\AC2\) BR2.3(\AC2\) L2.2
N12371737: C38.2 J3.1 RL1.3 RT1.1
N12371917: C35.2 L1.3 L4.3 R84.1 R86.2 RV1.2
N12371921: C36.2 C37.2 L1.4 L2.1 R43.2 R84.2
N12372235: D7.2 Q10.3 RL1.2
N12372625: T2.4 U6.13
N12372637: R47.2 R49.1
N12372641: C48.1 R55.2 R57.1 U6.7
N12372649: C43.1 R53.1 U6.9
N12372683: C42.1 R54.1 U6.6
N12372755: R48.2 R50.1
N12372759: R50.2 R51.1
N12372767: C45.1 R51.2 R56.1 U6.5(\V\)
N12372775: R49.2 R55.1
N12372865: C47.1 Q2.2(\EMITTER\) U6.1
N12372869: C42.2 C43.2 C44.2 C45.2 C46.2 C47.2 C48.2 R53.2 R56.2 R57.2 U6.4 VR3.2
N12372873: C44.1 U6.3
N12373065: C46.1 R54.2
N12432169: FL4.1 Q9.3 Q11.2
N12432631: Q6.1 R20.2 R23.1
N12432635: Q9.1 R27.2 R31.1
N12449925: D4.2 R58.1
N12454383: Q2.3 R52.2 R71.1
N12461790: D7.1 R44.2
N12462026: Q10.1 R45.1 R46.1
N12462864: D2.2 U1.9
N12465647: C8.1 C58.2 T1.3
N12471388: Q4.3 R10.2 R12.1
N12471420: Q4.1 R12.2 VR4.1
N12471928: C10.1 D6.1 R10.1
N12472447: Q7.1 R24.2 VR6.1
N12472558: Q7.3 R22.1 R24.1
N12474001: D1.2 T1.4
N12474629: C3.1 D1.1 Q1.3 R2.1
N12474978: Q1.1 R2.2 VR1.1
N12551412: R42.2 U5.1 U5.2 U5.3 U5.4
N12551460: R43.1 U5.5 U5.6 U5.7 U5.8(\NC8\)
N12570782: R64.2 R73.1 U1.2
N12570914: R63.2 R64.1
N12570918: R63.1 R65.2
N12631063: Q2.1 R71.2 VR3.1
N12672110: C54.1 T1.12
N12720122: Q1.2(\EMITTER\) R81.2
N12721764: D11.1 R52.1
N12722777: C60.1 F1.2 L4.1 R85.1
N12722869: C60.2 L4.2 R86.1 RL1.4(\NO\) RT1.2
N12733627: C70.1 GND1.1 L5.4 R87.2
N12734004: C70.2 L5.3 R88.2 UNK+60V1.1
N12796192: R40.1 U4.6(\PS\)

Pads without a net: T1 2 9 10; T2 1 2 5 7 8 9 10 11 12; U1 1 3 16 17 18; U4 13 24; U6 14

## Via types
v1: diameter 0.813, hole 0.508, TOP to BOTTOM, 8 vias
v2: diameter 0.61, hole 0.457, TOP to BOTTOM, 23 vias
v3: diameter 1.143, hole 0.61, TOP to BOTTOM, 1 via
v4: diameter 1.524, hole 0.889, TOP to BOTTOM, 4 vias

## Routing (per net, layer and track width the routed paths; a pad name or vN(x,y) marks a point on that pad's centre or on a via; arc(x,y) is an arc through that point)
5VL: length 58.4
  TOP w0.508: 23.8,35.96 23.88,35.88 23.88,28.02 v1(23.93,27.97)
  TOP w0.762: U1.7 23.8,35.96 23.7,36.05
  BOTTOM w0.381: C30.1 67.5,27.89 68.45,27.89 69.01,27.33 U4.15
  BOTTOM w0.762: v1(23.93,27.97) 23.95,27.95 C30.1
  BOTTOM w1.27: U1.7 23.7,34.77 C14.1
5VS: length 2.2
  BOTTOM w0.381: U4.1 83.21,36.23 C31.1
BM: length 88.9
  BOTTOM w0.508: D2.1 22.38,25.02 20.35,27.05 9.04,27.05 3.45,32.64 3.45,63.07 8.66,68.28 27.41,68.28 31.64,72.5 R45.2
BOOST_OP_POS: length 127.2
  TOP w0.508: 77.12,57.99 75.14,59.97 v1(29.59,59.97)
  TOP w1.27: C40.1 77.5,57.25 76.79,57.96
  TOP w2.032: C40.1 77.12,57.99
  BOTTOM w0.508: R65.1 5.51,38.15 5.46,38.2 5.46,52.3 13.13,59.97 v1(29.59,59.97)
  BOTTOM w0.762: C61.1 132.59,66.85 D8.1 127.56,70.87
  BOTTOM w2.54: C40.1 75.77,55.17 63.65,55.17 C58.1
BP_RELAY: length 141.8
  BOTTOM w0.508: C39.1 47.02,79.44 ; 47.02,79.44 47.02,80.63 RL1.1 ; 47.02,79.44 R44.1 36.51,79.44 26.8,69.72 7.85,69.72 1.65,63.53 1.65,26.59 17.94,10.3 R82.1
BPP: length 152.2
  TOP w0.508: v2(24.03,19.53) 20.17,19.53 6.63,33.07 6.63,51.33 v2(6.65,51.36) 6.65,56.69 11.1,61.14 55.71,61.14 v1(69.43,74.85)
  BOTTOM w0.508: v1(69.43,74.85) 70.24,74.04 D11.2 ; D4.1 27.87,19.53 ; 27.87,19.53 45.79,19.53 R81.1 45.8,19.78 45.8,20.8 46.79,21.79 C12.1 ; 27.87,19.53 R6.2 v2(24.03,19.53)
  BOTTOM w0.762: D3.2 v2(6.65,51.36)
BPS: length 89.6
  TOP w0.381: v2(109.42,24.69) 108.58,23.85 91.8,23.85 v2(90.81,24.84)
  BOTTOM w0.381: Q4.2 100.11,28.01 100.11,28.02 93.33,28.02 ; 90.75,28.02 93.33,28.02 ; 93.33,28.02 Q7.2 ; U4.7 85.4,29.58 86.01,28.98 C24.1
  BOTTOM w0.508: C24.1 89.79,28.98 90.81,27.96 v2(90.81,24.84) 90.81,19.89 107.59,3.1 J8.3 ; v2(109.42,24.69) 109.42,28.37 110.01,28.96 R27.1 110.94,29.11 122.28,29.11 R20.1
CC_COMP: length 54.7
  BOTTOM w0.254: J8.6 99.97,2.11 98.83,0.97 96.7,0.97 95.38,2.29 95.38,10.67 80.75,25.3 80.75,31.06 81.51,31.83 U4.4
  BOTTOM w0.381: U4.4 84.15,31.83 84.18,31.8 84.29,31.8 84.31,31.78 84.86,31.78 85.65,32.57 85.65,33.39 86.46,34.19 C25.1
  BOTTOM w0.508: R34.1 90.07,34.57 R74.1 89.68,34.19 C25.1
CC_FB: length 48.3
  BOTTOM w0.254: J8.7 97.43,9.89 81.9,25.43 81.9,25.47 81.33,26.04 81.33,30.58 81.83,31.08 U4.5
  BOTTOM w0.381: R16.1 86.33,32 85.41,31.08 U4.5
  BOTTOM w0.508: R16.1 87.51,30.85 87.94,30.43 91.97,30.43 92.24,30.16 R13.2
FL: length 57.5
  TOP w0.508: v4(21.79,28.19) 21.82,28.22 21.82,36.04 U1.6
  TOP w0.762: 21.8,36.05 21.64,35.89 U1.6
  BOTTOM w0.381: U4.14 23.41,26.58 v4(21.79,28.19)
GD: length 26.2
  TOP w1.27: C12.2 41.12,24.33 U1.10
  BOTTOM w0.762: C7.2 28.5,34.19 29.4,35.09 U1.10
GP: length 16.3
  TOP w0.508: U1.4 v4(18,29.13) v1(18,25.22)
  BOTTOM w0.508: Q3.2 18.01,21.71 R9.2 18.01,24.33 18,24.34 v1(18,25.22) ; 16.36,33.88 16.31,33.83 R73.2
  BOTTOM w0.762: 17.96,33.88 16.36,33.88
  BOTTOM w1.27: 18.03,36.02 U1.4
GSA: length 260
  TOP w0.508: 88.62,25.72 88.62,26.31 89.34,27.03 122.61,27.03 124.59,29.01 Q5.3 ; 88.62,25.72 v2(88.62,25.67) ; 88.62,25.72 125.13,25.72 126.92,23.93 126.92,19 Q11.3 ; J8.4 104.13,4 104.13,4.1 88.62,19.61 v2(88.62,25.67) ; v2(88.62,25.67) 92.32,21.97 103.84,21.97 107.54,18.26 C10.2 ; J8.2 110.08,3.12
  TOP w0.762: C15.2 97.6,49.88 97.87,50.15 131.99,50.15 C17.2
  TOP w1.27: C10.2 104.32,16.71 T1.8
  BOTTOM w0.381: U4.12 83.86,25.83 84.39,25.29 85.53,25.29 85.91,25.67 C24.2
  BOTTOM w0.508: VR4.2 104.7,17.41 105.4,16.71 C10.2 ; VR6.2 99.26,21.77 T1.8 ; J8.2 110.13,2.08 110.67,1.55 118.87,1.55 130.12,12.8 130.12,31.78 132.48,34.13 132.83,34.13 R18.1 ; 88.69,25.67 v2(88.62,25.67) C24.2
  BOTTOM w0.762: R28.1 127.21,18.3 125.65,16.74 Q11.3 ; Q5.3 125.92,34.5 125.92,34.52 R19.1
GSB: length 47.2
  BOTTOM w0.381: C26.2 93.71,36.08 93.71,32.75 93.23,32.27 C23.2 ; U4.2 84.28,33.33 85.14,34.19 85.14,36.03 C31.2
  BOTTOM w0.508: T1.11 99.77,37.77 R75.2 97.28,37.77 96.22,38.84 C71.2 93.83,38.84 92.35,40.31 85.91,40.31 85.4,39.8 C31.2
  BOTTOM w0.762: v1(92.08,38.18) 93.14,37.11 C26.2 93.05,36.58 89.94,36.58 R74.2 89.68,36.33 C25.2 87.48,36.33 ; C31.2 85.44,36.33 87.48,36.33 ; 87.48,36.33 87.48,37.72 86.72,38.48 R40.2 ; C23.2 91.78,32 R16.2
HVOUTP: length 94
  TOP w0.508: J8.1 112.7,3.1 ; 112.7,3.1 112.7,3.07 ; 112.7,3.1 112.7,5.41 115.39,8.11 v2(115.39,11.43) 132.8,11.43 L5.2
  BOTTOM w0.508: R22.2 102.94,29.6 115.39,17.14 v2(115.39,11.43)
  BOTTOM w0.762: C69.2 134.16,13.15 134.52,12.8 L5.2 135.94,11.02 141.65,11.02 R88.1 ; C68.2 145.53,33.28 C63.2 147.93,33.3 149.5,34.87 149.5,39.45 ; C23.1 95.52,32.09 R13.1 97.85,30.16 R22.2 ; C65.2 137.55,51.78 C17.1
IBSENSE: length 111.8
  BOTTOM w0.508: R18.2 131.59,30.85 131.01,30.27 131.01,11.91 119.71,0.61 104.44,0.61 102.51,2.54 J8.5
  BOTTOM w0.762: C64.1 149.34,55.05 151.61,52.78 151.61,34.39 146.69,29.46 135.83,29.46 ; C63.1 140.84,33.3 138.43,30.89 R60.2 ; C63.1 143.38,31 C68.1 ; C63.1 143.4,33.28 ; R87.1 134.18,27.81 L5.1 134.16,27.79 134.52,27.79 134.16,27.44
IS: length 6.4
  BOTTOM w0.508: C28.2 95.93,41.1 95.96,41.07 C71.1 98.09,40.97 98.12,41 ; R75.1 98.12,41 ; 98.12,41 C54.2
OVP: length 32.3
  BOTTOM w0.508: VR2.2 R7.1
  BOTTOM w0.762: VR2.2 50.01,16 R11.1
PE_GND: length 146.3
  BOTTOM w0.762: C65.1 144.56,62.55 146.57,64.56 ; 146.57,64.56 148.91,64.56 C64.2 148.71,64.71 ; 146.57,64.56 C61.2 150.86,71.14 C62.1 150.86,109.95 146.96,113.84 59.89,113.84 C37.1
PG_PFS: length 164.3
  TOP w0.508: v2(20.78,18.49) 17.3,18.49 3.96,31.83 3.96,56.36 10.13,62.53 54.41,62.53 68.5,76.63 109.19,76.63 110.1,75.73 U6.8
  BOTTOM w0.508: R72.1 20.8,18.52 v2(20.78,18.49)
RTN: length 141.1
  TOP w0.762: C62.2 137.78,68.81 C41.2
  TOP w1.27: C8.2 46.02,45.01 46.02,33.48 50.24,29.26 56.21,29.26 T1.5
  BOTTOM w0.508: C39.2 39.9,76.17 39.17,75.45 Q10.2 37.03,75.45 R46.2 ; C8.2 50.66,49.57 50.72,49.5
  BOTTOM w1.27: C40.2 58.93,76.17 C39.2 ; 112.03,76.54 U6.10 112.03,74 112.98,73.05 112.98,71.53 115.69,68.81 C41.2
  BOTTOM w1.524: C40.2 81.5,64.33 C15.1
VRECT: length 47.6
  TOP w1.27: D8.2 135.18,79.76 113.74,101.19 110.64,101.19 T2.3
  BOTTOM w1.27: 110.26,101.12 T2.3 ; D8.2 135.18,72.28 R48.1
  vias: v4(102.42,104.47) v4(105.72,104.47)
N4285024: length 9.6
  BOTTOM w0.508: R1.1 23.67,55.8 C1.2
  BOTTOM w0.762: C1.2 24.71,53.67 25.6,52.78 25.6,49.36 U1.13
N4285032: length 8.9
  BOTTOM w0.762: C4.1 C5.1 17.17,55.19 R3.1 19.08,55.19 19.96,56.08 R1.2
N4285050: length 3
  BOTTOM w0.762: 21.47,50.67 C2.2 21.54,48.25 U1.15
N4286456: length 2.8
  BOTTOM w0.762: 23.68,48.02 U1.14 23.68,48.02 ; 23.68,48.02 C2.1
N4298336: length 4.1
  BOTTOM w2.032: T1.6 65.2,13.36 D5.2
N4344251: length 17.6
  TOP w0.508: v1(19.9,25.22) U1.5
  BOTTOM w0.508: R72.2 22.3,20.65 Q3.3 20.17,22.2 20.14,22.23 R9.1 20.14,24.87 19.9,25.11 v1(19.9,25.22)
N4347891: length 17.1
  TOP w0.508: v2(25.6,23.16) 25.6,25.86 U1.8
  BOTTOM w0.508: R6.1 25.6,21.69 v2(25.6,23.16)
  BOTTOM w0.762: U1.8 25.6,34.98 26.37,34.21 C7.1
N4369660: length 12.3
  TOP w0.381: v2(84.53,32.58) 84.6,32.58 86.03,34.01 v2(86.03,41.45)
  BOTTOM w0.381: U4.3 v2(84.53,32.58)
  BOTTOM w0.508: R36.1 86.59,42.01 v2(86.03,41.45)
N4383576: length 42.4
  TOP w0.381: v2(85.5,28.08) 88.3,30.89 118.34,30.89 121.11,28.12 v2(121.8,28.12)
  BOTTOM w0.381: U4.9 v2(85.5,28.08)
  BOTTOM w0.762: R29.2 v2(121.8,28.12)
N4398139: length 2.9
  BOTTOM w0.508: Q6.3 119.71,34.52 119.74,34.54
N4403571: length 44.5
  TOP w0.381: v2(84.38,28.83) 84.48,28.83 87.45,31.8 116.84,31.8 119.41,34.37 v2(119.41,38.07)
  BOTTOM w0.381: v2(84.38,28.83) U4.8
  BOTTOM w0.508: R21.2 118.72,38.76 v2(119.41,38.07)
N4411199: length 2
  BOTTOM w0.762: R38.1 93.78,42.04 R37.1
N4411203: length 2.2
  BOTTOM w0.508: R38.2 93.83,44.19 94.08,44.44 C28.1
N4415619: length 2.1
  BOTTOM w0.762: C26.1 95.27,34.65 R34.2
N4433947: length 8
  BOTTOM w0.508: 124.59,21.77 124.63,21.8 124.64,21.8
  BOTTOM w0.762: 125.1,22.26 125.1,22.25 124.88,22.03 ; 125.1,22.26 124.64,21.8 ; 125.1,22.26 R29.1 ; 124.88,22.03 Q11.1 ; 124.88,22.03 R28.2
N4539125: length 5.9
  BOTTOM w0.762: R19.2 126.49,38.25 Q5.1 123.86,38.25 R21.1
N4545785: length 4
  BOTTOM w0.762: D3.1 15.52,57.33 R3.2
N11972126: length 29
  BOTTOM w0.508: R58.2 43.62,14.29 R82.2
  BOTTOM w0.762: C13.1 48.45,13.35 VR2.1 45.53,12.5 R82.2
  BOTTOM w1.27: D5.1 58.02,13.35 C13.1
N12003586: length 2.3
  BOTTOM w0.508: Q3.1 17.93,19.66 R7.2
N12025663: length 31.1
  TOP w0.381: v2(108.83,29.94) 88.84,29.94 86.24,27.33 v2(84.4,27.33)
  BOTTOM w0.381: v2(84.4,27.33) U4.10
  BOTTOM w0.508: R25.2 110.21,32.59 108.83,31.2 v2(108.83,29.94)
N12156031: length 5
  BOTTOM w1.27: D6.2 102.44,13.51 T1.7
N12157735: length 4.5
  BOTTOM w0.762: R32.1 R31.2 115.08,26.77 115.08,26.33 Q9.2
N12157737: length 39
  TOP w0.381: v2(84.89,26.49) 86.87,26.49 89.38,29.01 118.56,29.01 v2(119.43,28.14)
  BOTTOM w0.381: v2(84.89,26.49) 84.79,26.49 84.7,26.58 U4.11
  BOTTOM w0.762: R32.2 v2(119.43,28.14)
N12157825: length 3.9
  BOTTOM w0.508: R25.1 113.49,32.59 R23.2 115.7,32.61 Q6.2
N12357991: length 1.8
  BOTTOM w0.762: R37.2 90.4,42.01 R36.2
N12371579: length 28.8
  TOP w2.032: RV1.1 26.31,87.83 33.02,94.54 C35.1
  BOTTOM w0.762: L4.4 24.02,99.15 R85.2 ; R83.1 41.38,103.12 L1.1
N12371615: length 7.1
  BOTTOM w0.762: R83.2 48.18,103.12 L1.2
  BOTTOM w1.27: 50.32,100.81 L1.2
N12371639: length 14.8
  BOTTOM w2.54: L2.2 77.5,93.45 BR2.3 88.62,93.45 88.64,93.43 BR1.3
N12371737: length 34.6
  TOP w0.762: J3.1 3.57,81.67 6.93,85.04 6.93,100.97 9.7,103.73 C38.2
  BOTTOM w2.032: RT1.1 7.19,77.27 J3.1
N12371917: length 10.5
  BOTTOM w0.762: R86.2 23.68,91.81 L4.3 ; L1.3 41.95,87.93 R84.1
N12371921: length 19.1
  TOP w2.032: C37.2 63.17,100.02 L2.1
  BOTTOM w0.762: 44.58,87.93 47.61,87.93 L1.4 50.49,90.82
N12372235: length 7.2
  BOTTOM w0.508: RL1.2 44.11,73.05 42.65,74.51 D7.2 Q10.3
N12372637: length 2.2
  BOTTOM w0.762: R47.2 104.09,63.89 R49.1
N12372641: length 18.3
  TOP w0.508: v2(110.5,67.81) 110.12,67.42 v1(100.22,67.42)
  BOTTOM w0.508: v2(110.5,67.81) 110.5,68.17 110.46,68.21 ; 110.46,68.21 109.41,68.21 C48.1 ; 110.46,68.21 R57.1
  BOTTOM w0.762: U6.7 109.13,68.49 C48.1 ; R55.2 100.19,67.45 v1(100.22,67.42)
N12372649: length 7.8
  BOTTOM w0.762: C43.1 113.75,67.2 113.76,67.21 ; 113.76,67.21 113.76,68.33 111.06,71.03 U6.9 ; 113.76,67.21 115.61,67.21 R53.1
N12372683: length 4.4
  BOTTOM w0.508: R54.1 C42.1 108.17,76.37 U6.6
N12372755: length 2.8
  BOTTOM w1.27: R50.1 R48.2
N12372759: length 2.8
  BOTTOM w1.27: R50.2 124.69,78.93 R51.1
N12372767: length 26.2
  TOP w0.508: v1(119.71,70.89) 118.41,69.6 107.82,69.6 107.2,70.22 U6.5
  BOTTOM w0.762: R51.2 121.39,75.41 119.71,73.74 v1(119.71,70.89) ; U6.5 107.2,68.29 107.24,68.25 C45.1 107.21,68.22 107.2,68.21 R56.1
N12372775: length 2.5
  BOTTOM w0.762: R55.1 100.2,64.15 R49.2
N12372865: length 22.8
  TOP w0.508: v2(85.33,71.49) 86.94,73.1 101.04,73.1 102.65,74.71 U6.1
  BOTTOM w0.508: v2(85.33,71.49) 85.33,72.56 Q2.2
  BOTTOM w0.762: C47.1 101.98,74.71 U6.1
N12372869: length 50.4
  TOP w0.508: v2(88.8,71.68) 102.51,71.68 105.36,74.52 106.05,74.52 U6.4
  BOTTOM w0.508: VR3.2 88.04,70.92 v2(88.8,71.68) ; C46.2 105.58,76.82 C42.2 105.63,76.44 106.24,75.83 U6.4 106.24,74.45 105.43,73.64 104.71,73.64 102.93,71.87 C47.2 101.27,71.77 101.28,71.76 C44.2 101.28,68.81 104.01,66.08 R56.2
  BOTTOM w0.762: R56.2 105.36,66.1 105.38,66.08 107.2,66.08 107.21,66.09 C45.2 107.26,66.12 109.37,66.12 C48.2 111.29,66.09 R57.2 112.05,66.08 113.07,65.06 C43.2 115.52,65.06 115.54,65.09 R53.2
N12372873: length 2.6
  BOTTOM w0.762: U6.3 103.56,70 103.47,70 C44.1
N12373065: length 2.2
  BOTTOM w0.508: C46.1 105.61,78.96 R54.2
N12432169: length 5.3
  BOTTOM w0.762: Q9.3 116.11,22.73 FL4.1
N12432631: length 6.1
  BOTTOM w0.508: R23.1 115.96,30.73 Q6.1 117.6,30.56 R20.2
N12432635: length 4
  BOTTOM w0.762: 111.89,26.8 112.97,26.8 R31.1 ; 111.89,26.8 Q9.1 ; 111.89,26.8 110.82,26.8 R27.2
N12449925: length 2.4
  BOTTOM w0.508: R58.1 29.98,17.41 27.89,17.41 D4.2
N12454383: length 4.5
  BOTTOM w0.508: Q2.3 82.19,72.64 R71.1 80.99,72.63 R52.2
N12461790: length 2.2
  BOTTOM w0.508: D7.1 R44.2
N12462026: length 3.8
  BOTTOM w0.508: R45.1 R46.1 36.93,73.57 Q10.1
N12462864: length 12.2
  TOP w0.508: v2(27.53,25.02) 27.5,25.05 U1.9
  BOTTOM w0.508: v2(27.53,25.02) D2.2
N12471388: length 7.3
  BOTTOM w0.508: R10.2 105,24.31 R12.1
  BOTTOM w0.762: Q4.3 R12.1
N12471420: length 7
  BOTTOM w0.508: R12.2 101.22,23.16 102.39,22 VR4.1
  BOTTOM w0.762: Q4.1 101.19,26.01 101.19,24.33 R12.2
N12471928: length 8.3
  BOTTOM w1.27: R10.1 108.86,18.95 C10.1 111.1,13.93 D6.1
N12472447: length 6.4
  BOTTOM w0.762: Q7.1 93.4,25.27 94.74,23.93 R24.2 96.43,23.05 VR6.1
N12472558: length 5.3
  BOTTOM w0.762: R24.1 98.57,26.14 R22.1 95.7,26.3 Q7.3
N12474001: length 4.4
  BOTTOM w1.27: T1.4 66.11,24.54 D1.2
N12474629: length 8.5
  BOTTOM w0.762: Q1.3 51.08,21.84 R2.1 53.77,21.87 55.75,21.87 C3.1 55.87,22.92 D1.1
N12474978: length 4.5
  BOTTOM w0.762: Q1.1 R2.2 53.77,19.69 56.29,19.69 VR1.1
N12570782: length 4.5
  BOTTOM w0.508: R64.2 14.12,33.81 R73.1 14.2,33.89 U1.2
  BOTTOM w0.762: 14.17,36.02 U1.2
N12570914: length 2.2
  BOTTOM w0.508: R63.2 7.67,33.81 R64.1
N12570918: length 2.2
  BOTTOM w0.508: R63.1 R65.2
N12631063: length 6.3
  BOTTOM w0.508: R71.2 85.01,74.78 Q2.1 85.37,74.42 VR3.1
N12672110: length 3.8
  BOTTOM w0.508: T1.12 101.14,44.22 C54.1
N12720122: length 2
  BOTTOM w0.508: R81.2 48.1,19.71 Q1.2
N12721764: length 2.3
  BOTTOM w0.508: R52.1 76.58,74.05 D11.1
N12722777: length 5.3
  BOTTOM w0.762: R85.1 19.56,99.15 16.94,101.77 L4.1
N12722869: length 5.8
  BOTTOM w0.762: L4.2 19.6,91.81 R86.1
N12733627: length 13.8
  BOTTOM w0.762: R87.2 150.15,27.81 L5.4 ; L5.4 150.26,27.69 150.42,27.69 150.06,27.34 ; L5.4 150.16,23.34 C70.1
N12734004: length 15.3
  BOTTOM w0.762: C70.2 150.16,13.35 150.06,13.25 150.42,12.9 150.26,12.9 L5.3 150.16,12.44 148.82,11.1 R88.2
N12796192: length 13.7
  TOP w0.381: v2(84.45,30.33) 90.58,36.45 v3(90.58,38.48)
  BOTTOM w0.381: U4.6 84.45,30.33 v2(84.45,30.33)
  BOTTOM w0.762: v3(90.58,38.48) R40.1

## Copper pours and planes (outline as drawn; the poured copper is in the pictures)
BOOST_OP_POS on TOP: 84.75,61.2 77.77,54.23 77.68,54.23 74.91,56.99 73.59,56.99 73.57,56.98 22.44,56.98 12.64,47.18 12,47.18 11.38,47.8 11.38,48.83 21.54,58.98 76.34,58.98 76.43,59.06 81.73,64.36 94.08,64.36 94.11,64.34 94.11,64.28 94.11,61.59 94.1,61.59 93.71,61.2
BOOST_OP_POS on TOP: 117.5,73.81 120.09,73.81 121.51,72.39 123.88,72.39 125.91,70.36 129.03,70.36 129.11,70.43 129.11,75.21 128.47,75.84 117.5,75.84 117.12,75.46 117.12,74.19
BOOST_OP_POS on BOTTOM: 94.16,64.21 94.41,64.21 96.22,62.41 107.34,62.41 108.2,63.27 119.74,63.27 126.01,69.55 126.01,73.36 126.16,73.51 129.18,73.51 129.18,69.29 120.45,60.55 93.42,60.55 91.9,62.08 91.9,64.31 94.06,64.31
GP on BOTTOM: 17.69,36.79 18.32,36.79 18.73,36.37 18.73,34.26 19.08,33.91 20.71,33.91 20.71,32.62 22.55,30.78 71.15,30.78 71.2,30.73 71.2,28.07 69.42,28.07 68.22,29.26 66.95,29.26 66.95,29.26 20.42,29.26 17.26,32.42 17.26,36.36
GS on BOTTOM (solid shape): 7.65,5.05 1.02,5.05 1.02,8.18 7.65,8.18
GSA on BOTTOM (solid shape): 132.05,41.33 128.93,41.33 128.93,47.96 132.05,47.96
GSA on BOTTOM (solid shape): 95.7,51.04 97,49.75 97,49.35 96.29,48.64 95.68,48.64 94.52,49.81 94.52,49.86 94.12,50.65 94.91,50.25 94.52,51.04 95.31,50.65 94.91,51.44
GSA on TOP: 134.94,37.96 135.72,37.17 135.72,35.91 129.34,29.52 129.34,18.01 126.9,15.57 124.15,15.57 123.53,16.19 123.53,17.27 124.14,17.88 126.71,17.88 127.53,18.7 127.53,28.6 123.43,32.71 123.43,33.67 124.06,34.31 125.24,34.31 128.89,37.96
GSA on BOTTOM: 130.68,51.03 133.96,51.03 136.65,48.34 145.57,48.34 145.62,48.29 145.62,48.27 145.63,48.27 146.15,47.75 146.15,43.54 146.15,43.54 142.82,43.54 141.88,44.48 135.61,44.48 135,43.87 135,40.61 137.67,37.95 146.41,37.95 147.98,36.37 147.98,35.15 147.37,34.54 139.88,34.54 138.7,33.37 132.17,33.37 128.5,37.03 128.5,48.84
HVOUTP on BOTTOM (solid shape): 142.19,13.82 141.35,13.54 142.19,13.26 141.35,12.98 142.19,12.7 141.35,12.42 134.37,12.42 134.16,12.62 134.16,13.92 134.34,14.1 141.35,14.1
HVOUTP on TOP: 137.05,12.73 137.05,21.04 147.4,31.39 151.41,31.39 151.73,31.72 151.73,50.98 150.34,52.37 137.52,52.37 136.68,51.54 136.68,40.16 138.22,38.61 138.28,38.56 138.66,38.17 138.66,34.34 136.91,32.59 136.91,25.73 131.98,20.8 131.98,11.76 132.57,11.17 135.48,11.17 ; 2 cut-outs
HVOUTP on BOTTOM: 135.84,43.46 141.3,43.46 142.88,41.88 146.66,41.88 147.85,43.07 147.85,44.99 147.99,45.14 149.38,45.14 149.89,44.63 149.89,39.29 149.17,39.29 148.78,39.69 140.4,39.69 139.35,38.64 138.2,38.64 135.79,41.05 135.79,43.41
HVOUTP on BOTTOM: 127.25,55.52 135.38,55.52 136.65,54.25 146.63,54.25 150.22,50.67 150.22,50.57 148.84,49.2 137.08,49.2 133.9,52.39 130.28,52.39 127.33,49.44 127.33,43.41 125.58,41.66 125.55,41.66 125.48,41.58 110.95,41.58 109.8,42.73 109.8,48.58 110.9,49.68 121.41,49.68
IBSENSE on BOTTOM (solid shape): 137.24,26.31 141.4,26.31 142.24,26.04 141.4,25.76 142.24,25.48 141.4,25.2 142.24,24.92 141.4,24.64 135.81,24.64 134.09,26.37 134.09,28.24 135.31,28.24
IBSENSE on BOTTOM: 138.68,31.65 138.68,27.51 138.61,27.43 136.86,27.43 134.8,25.37 134.8,20.75 133.55,20.75 133.53,20.78 133.53,25.43 131.93,27.03 131.93,31.65
PE_GND on BOTTOM: 1.21,108.81 3.44,108.81 7,112.38 59.88,112.38 60.43,112.93 60.43,113.83 59.82,114.44 1.43,114.44 0.57,113.59 0.57,109.46
RTN on BOTTOM (solid shape): 43.59,64.31 36.96,64.31 36.96,67.44 43.59,67.44
RTN on BOTTOM (solid shape): 97.49,77.98 90.86,77.98 90.86,81.1 97.49,81.1
RTN on BOTTOM (solid shape): 88.85,58.06 89.38,58.06 90.03,57.42 90.03,56.79 89.99,56.75 90.39,55.96 89.6,56.36 89.99,55.57 89.2,55.96 89.6,55.17 88.81,55.57 88.23,56.14 87.91,56.47 87.91,57.19 88.82,58.09
RTN on TOP: 95.81,69.7 99.24,66.27 118.31,66.27 121.72,69.67 122.66,69.67 123.39,68.94 123.39,67.23 119.79,63.63 98.04,63.63 95.25,66.42 76.12,66.42 71.91,62.2 69.7,62.2 68.42,63.49 68.42,65.33 72.78,69.7
RTN on BOTTOM: 99.52,95.07 104.52,95.07 105.59,94.01 105.59,91.26 112.67,84.18 112.67,76.28 112.14,75.74 111.76,75.74 110.41,77.09 110.41,79.81 103.38,86.84 103.38,90.14 103.2,90.32 103,90.32 102.82,90.14 102.82,86.94 101.09,85.22 101.09,76.63 98.3,73.84 98.3,71.73 93.75,67.18 91.82,67.18 90.88,68.12 90.88,75.64 92.1,76.86 97.61,76.86 98.09,77.34 98.09,87.1 101.12,90.12 101.12,90.4 100.99,90.53 100.69,90.53 97.49,87.33 97.49,77.8 83.03,77.8 80.19,80.65 80.19,88.95 81.13,89.89 94.34,89.89
RTN on BOTTOM: 60.02,22.58 59.08,22.58 58.66,22.16 58.66,19.16 57.66,18.16 52.2,18.16 51.59,17.55 51.59,15.29 51.74,15.14 58.39,15.14 58.85,15.6 58.88,15.6 60.95,17.67 66.71,17.67 67.72,18.67 67.72,20.07 66.83,20.96 61.65,20.96
RTN on BOTTOM: 29.21,46.94 28.6,47.55 28.6,48.36 36.22,55.98 36.22,67.46 36.68,67.92 70.43,67.92 72.77,65.58 72.77,62.94 69.18,59.35 60.49,59.35 52.22,51.08 52.22,48.31 50.85,46.94
VRECT on BOTTOM: 102.92,100.74 101.47,100.74 100.18,102.03 82.19,102.03 81.86,102.36 81.86,104.98 82.19,105.31 102.74,105.31 103.17,104.88 103.17,102.62 103.53,102.26 103.53,101.35
VRECT on BOTTOM: 109.7,105.28 112.12,102.87 112.09,102.84 112.09,100.41 111.2,99.52 109.12,99.52 104.88,103.76 104.88,104.83 105.33,105.28
N4285050 on TOP: 67.63,43.2 67.63,48.45 61.23,54.85 25.52,54.85 21.05,50.37 21.05,47.68 21.46,47.27 22.12,47.27 22.53,47.67 22.53,48.99 26.34,52.8 60.28,52.8 64.57,48.51 64.57,43.25 64.66,43.16 67.59,43.16
N4285050 on BOTTOM: 22.16,54.3 22.16,50.12 22.17,50.11 18.71,50.11 18.65,50.18 18.65,53.6 18.67,53.62 20.21,53.62 20.9,54.3
N4398139 on BOTTOM: 118.87,36.93 122.5,36.93 123.27,36.17 123.27,35.18 122.34,34.25 110.5,34.25 109.78,34.98 109.78,39.37 110.97,40.56 115.24,40.56
N12371547 on BOTTOM: 3.68,100.43 3.68,92.96 2.95,92.23 1.05,92.23 0.41,92.87 0.41,100.51 0.84,100.94 3.17,100.94
N12371579 on BOTTOM (solid shape): 43.54,101.24 42.7,100.97 43.54,100.69 42.7,100.41 43.54,100.13 42.7,99.85 38.58,99.85 38.2,100.23 38.2,101.35 38.38,101.52 42.7,101.52
N12371579 on BOTTOM (solid shape): 26.76,102.58 26.77,102.59 27.05,102.59 27.13,102.51 27.13,101.09 26.95,100.91 22.63,100.91 21.79,101.19 22.63,101.47 21.79,101.75 22.63,102.03 21.79,102.31 22.63,102.59 26.75,102.59
N12371579 on BOTTOM: 28.17,105.03 36.83,105.03 40.16,101.7 40.16,100.03 39.62,99.49 26.7,99.49 25.32,100.87 25.32,102.18
N12371615 on BOTTOM (solid shape): 49.01,101.51 49.02,101.52 49.3,101.52 49.38,101.45 49.38,100.03 49.2,99.85 44.88,99.85 44.04,100.13 44.88,100.41 44.04,100.69 44.88,100.97 44.04,101.24 44.88,101.52 49,101.52
N12371615 on BOTTOM: 54.33,104.47 51.99,104.47 48.64,101.12 48.64,99.97 48.65,99.96 48.65,95.52 48.84,95.33 50.35,95.33 50.37,95.36 50.37,99.17 50.59,99.39 50.88,99.39 51.18,99.08 51.18,98.31 51.31,98.19 55.05,98.19 56.26,96.98 92.81,96.98 93.7,97.87 93.7,99.31 92.93,100.09 58.71,100.09
N12371737 on TOP: 2.13,83.31 4.6,83.31 7.29,80.62 25.68,80.62 26.82,81.76 28.45,81.76 29.31,80.9 29.31,80.21 27.36,78.26 3.48,78.26 1.17,80.57 1.17,82.35
N12371917 on BOTTOM (solid shape): 43.54,91.39 42.7,91.11 43.54,90.83 42.7,90.55 43.54,90.27 42.7,89.99 38.58,89.99 38.2,90.37 38.2,91.49 38.38,91.67 42.7,91.67
N12371917 on BOTTOM (solid shape): 27.09,95.59 27.1,95.61 27.38,95.61 27.46,95.53 27.46,94.11 27.28,93.93 22.96,93.93 22.12,94.21 22.96,94.49 22.12,94.77 22.96,95.05 22.12,95.33 22.96,95.61 27.08,95.61
N12371917 on BOTTOM: 31.16,92.05 39.52,92.05 40.28,91.29 40.28,90.17 39.34,89.23 35.95,89.23 34.95,88.23 34.95,82.76 34.23,82.04 33.37,82.04 32.68,82.72 32.68,86.67 25.37,93.99 25.37,95.28 26.13,96.05 27.16,96.05
N12371921 on BOTTOM (solid shape): 49.01,91.66 49.02,91.67 49.3,91.67 49.38,91.59 49.38,90.17 49.2,89.99 44.88,89.99 44.04,90.27 44.88,90.55 44.04,90.83 44.88,91.11 44.04,91.39 44.88,91.67 49,91.67
N12371921 on BOTTOM: 48.44,91.21 48.44,85.83 52.22,82.04 60.25,82.04 64.69,86.49 64.69,93.98 63.78,94.89 62.48,94.89 61.37,93.78 61.37,87.94 60.47,87.05 56.11,87.05 54.23,85.17 52.45,85.17 50.88,86.74 50.88,89.43 51.79,90.35 51.79,91.44 51.18,92.05 49.28,92.05
N12372625 on TOP: 108.94,92.48 108.94,94.46 109.58,95.1 111.2,95.1 116.61,89.69 116.61,77.77 115.57,76.73 115.57,74.14 115.24,73.81 114.48,73.81 114.29,74 114.29,75.58 114.27,75.59 114.27,87.15
N12432169 on BOTTOM: 115.32,24.43 121.26,24.43 122.15,23.55 122.15,20.83 123.27,19.71 123.27,18.52 121.39,16.64 117.35,16.64 114.48,19.51 114.48,23.6
N12465647 on BOTTOM: 66.7,36.2 49.78,36.2 49.3,35.71 49.3,33.6 49.86,33.05 66.34,33.05 67.51,34.21 67.51,35.38
N12551412 on BOTTOM (solid shape): 59.41,93.29 58.8,93.29 58.8,93.8 55.6,93.8 55.6,93.29 54.99,93.29 54.99,95.48 59.41,95.48
N12551412 on BOTTOM: 52.15,96.88 53.75,96.88 55.07,95.55 59.44,95.55 59.51,95.48 59.51,93.34 59.41,93.24 54.99,93.24 52.88,95.35 52.15,95.35
N12551460 on BOTTOM (solid shape): 55.63,89.76 58.83,89.76 58.83,90.27 59.44,90.27 59.44,88.09 55.02,88.09 55.02,90.27 55.63,90.27
N12551460 on BOTTOM: 59.44,90.3 54.74,90.3 52.73,88.29 52.73,86.77 54.23,86.77 55.5,88.04 59.41,88.04 59.44,88.06
N12722777 on BOTTOM (solid shape): 21.29,102.31 20.45,102.03 21.29,101.75 20.45,101.47 21.29,101.19 20.45,100.91 16.33,100.91 15.95,101.3 15.95,102.41 16.13,102.59 20.45,102.59
N12722777 on BOTTOM: 12.65,95.96 12.65,93.47 5.82,86.64 1.89,86.64 1.6,86.93 1.6,88.45 2,88.85 3.58,88.85 8.89,94.16 8.89,99.9 9.73,100.74 13.51,100.74 15.82,103.05 17.32,103.05 17.86,102.51 17.91,102.46 17.91,101.22
N12722869 on BOTTOM (solid shape): 21.62,95.33 20.78,95.05 21.62,94.77 20.78,94.49 21.62,94.21 20.78,93.93 16.66,93.93 16.28,94.31 16.28,95.43 16.46,95.61 20.78,95.61
N12722869 on BOTTOM: 15.34,91.59 9.11,85.36 9.11,83.74 10.46,82.4 16.28,82.4 21.87,76.81 21.87,74.72 21.55,74.4 18.25,74.4 16.13,76.52 14.91,76.52 14.24,75.84 14.24,74.58 16.81,72.01 24.05,72.01 25.22,73.18 25.22,78.71 18.52,85.42 15.01,85.42 14.71,85.73 14.71,86.89 18.16,90.35 18.16,95.05 17.17,96.04 16.1,96.04 15.34,95.28
N12733627 on BOTTOM (solid shape): 150.83,27.89 150.83,27.56 147.9,24.64 143.59,24.64 142.75,24.92 143.59,25.2 142.75,25.48 143.59,25.76 142.75,26.04 143.59,26.31 147.12,26.31 149.28,28.47 150.24,28.47
N12733627 on TOP: 145.2,16.78 145.2,10.8 140.54,6.14 140.54,1.93 139.29,0.69 137.11,0.69 137.1,0.68 134.2,0.68 133.25,1.63 133.25,6.73 139.46,12.95 139.46,20.03 148.87,29.44 151.36,29.44 151.84,28.96 151.84,23.42
N12734004 on BOTTOM (solid shape): 150.19,13.82 150.19,12.9 149.71,12.42 143.54,12.42 142.7,12.7 143.54,12.98 142.7,13.26 143.54,13.54 142.7,13.82 143.54,14.1 149.91,14.1
N12734004 on BOTTOM: 151.82,13.49 151.82,2.24 149.99,0.41 146.46,0.41 144.5,2.36 144.5,5.31 147.88,8.69 147.88,13.06 147.9,13.06 149.3,14.45 150.85,14.45

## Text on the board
Ref Des/Silkscreen Bottom: GP | FL | PP | PS | GSB | DER-984 | S/N | 2350 | REV E
Ref Des/Silkscreen Top: L | PE | N | FB | CMP | IS | GSA | BPS | HV
User.6: 16. 1 X SLOT | 15. 6 X PLATED SLOTS | 14.  FAB HOUSE LOGO,DATE CODE TO BE IN SILK SCREEN ONLY.DO NOT USE COPPER. | 17. 1 X BOARD CUTOUT | 13.  MATERIAL FR4 COPPER 2oz THICKNESS 0.062" | NOTES: PLEASE DELETE THESE PINS | CUTOUT | 4 PLATED | SLOTS
User.9: FIGURE | FINISHED_SIZE | 18.0 | 20.0 | 24.0 | 30.0 | 34.0 | 35.0 | 35.433 | 40.0 | 46.0 | 50.0 | 52.0 | 55.0 | 60.0 | 68.0 | 70.0 | 80.0 | 156.0 | 204.701 | DRILL CHART: TOP to BOTTOM | ALL UNITS ARE IN MILS | TOLERANCE_DRILL | +3.0/-3.0 | PLATED | NON-PLATED | QTY | 23 | 8 | 1 | 16 | 18 | 4 | 7 | 53 | 12 | 2 | 3 | 20 | 6 | 205 | TOTAL HOLES:
